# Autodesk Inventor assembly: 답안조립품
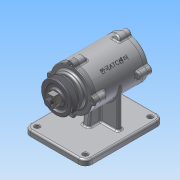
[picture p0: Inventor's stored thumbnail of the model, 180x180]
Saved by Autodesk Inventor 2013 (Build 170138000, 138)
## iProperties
Created: 2015-12
Part Number: 답안조립품
Document SubType Name: Assembly
Designer: Administrator
Mass: 2107.12 g
Surface Area: 1551.47 cm^2
Volume: 634.117 cm^3
Density: 3.32292 g/cm^3
Author: Administrator
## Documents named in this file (11)
- C:\Users\Administrator\Desktop\451208V1023\답안조립품.iam
- C:\Users\Administrator\Desktop\451208V1023\본체.ipt
- C:\Users\Administrator\Desktop\451208V1023\커버.ipt
- C:\Users\Administrator\Desktop\451208V1023\커버2.ipt
- C:\Users\Administrator\Desktop\451208V1023\볼트 M4 x 12.ipt
- C:\Users\Administrator\Desktop\451208V1023\오일실.ipt
- C:\Users\Administrator\Desktop\451208V1023\베어링 6204.ipt
- C:\Users\Administrator\Desktop\451208V1023\축.ipt
- C:\Users\Administrator\Desktop\451208V1023\키(4 x 4 x 12).ipt
- C:\Users\Administrator\Desktop\451208V1023\V-벨트풀리.ipt
- C:\Users\Administrator\Desktop\451208V1023\너트 M12x1.25.ipt
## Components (6 placed, 5 different names)
1. KS B 2804 D D - 20 32 8:1
2. KS B 2023 6204 - 20 x 47 x 14:1
3. KS B 2023 6204 - 20 x 47 x 14:2
4. KS B 1311 (I) 4 x 4 x 12:1 — 각도:1, 각도:2, 각도:3
5. V-벨트풀리:1 — 각도:2
6. KS B 1012 클래스 1 일반 - 미터 M12x1.25:1
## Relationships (3: Angle 3)
- 각도:1 [Angle]: KS B 1311 (I) 4 x 4 x 12:1
- 각도:2 [Angle]: KS B 1311 (I) 4 x 4 x 12:1 ↔ V-벨트풀리:1
- 각도:3 [Angle]: KS B 1311 (I) 4 x 4 x 12:1
